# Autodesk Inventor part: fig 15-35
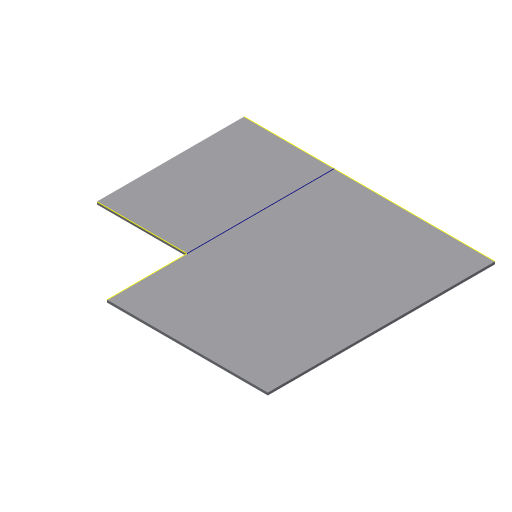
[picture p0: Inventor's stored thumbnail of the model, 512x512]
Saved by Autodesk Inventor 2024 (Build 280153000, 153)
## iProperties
Created: 2005-03
Part Number: fig 15-35
Document SubType Name: Sheet Metal
Designer: CADCIM
Manufacturer: Standard
Standards Organization: Custom
Density: 1 g/cm^3
Sheet Metal Rule: Default
Material: Generic
Appearance: Default
Author: CADCIM
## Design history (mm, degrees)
node "Face1"
  sketch "Sketch1"
    geometry: L1 (31.393, 35.714)-(-19.875, 35.714); L2 (-19.875, 35.714)-(-19.875, 5.625); L3 (-19.875, 5.625)-(-1.5, 5.625); L4 (-1.5, 5.625)-(-1.5, -10.705); L5 (-1.5, -10.705)-(31.393, -10.705); L6 (31.393, -10.705)-(31.393, 35.714)
    constraints: 12 end point, 4 parallel, 1 horizontal, 1 perpendicular
body "Solid1"
sketch "Sketch3"
  geometry: L1 (18.375, -30.089)-(18.375, 0); L2 (18.375, -46.42)-(18.375, -30.089) reference; L3 (18.375, -30.089)-(0, -30.089) reference; L4 (0, 0)-(51.268, 0) reference
  constraints: 3 point on line, 2 end point, 1 vertical
face "Plate1" dims "d1" = 0.5 (= Thickness)
other parameters: "Thickness" = 0.5, "BendRadius" = 0.5 (= Thickness), "BendReliefWidth" = 0.5 (= Thickness), "BendReliefDepth" = 0.25 (= 0.5 x Thickness), "CornerReliefSize" = 2 (= 4 x Thickness), "SeamGap" = 0.01, "MinimumRemnant" = 1 (= 2 x Thickness), "TransitionRadius" = 0.5 (= BendRadius), "d0" = 0.5 (= BendRadius), "JacobiRadiusSize" = 0.5 (= Thickness), "GapSize" = 0.5 (= Thickness)
